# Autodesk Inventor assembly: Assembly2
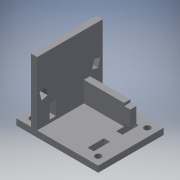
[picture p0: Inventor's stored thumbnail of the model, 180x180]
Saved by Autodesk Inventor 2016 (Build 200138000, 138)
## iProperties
Created: 2017-06
Part Number: Assembly2
Document SubType Name: Assembly
Designer: laboratorioesan
Author: laboratorioesan
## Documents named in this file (4)
- C:\Users\laboratorioesan\Desktop\Proyecto final\FAROS\Assembly2.iam
- C:\Users\laboratorioesan\Desktop\Proyecto final\FAROS\frontal_delantero.ipt
- C:\Users\laboratorioesan\Desktop\Proyecto final\FAROS\Part4.ipt
- C:\Users\laboratorioesan\Desktop\Proyecto final\FAROS\Part5.ipt
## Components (3 placed, 3 different names)
1. frontal_delantero:1 — Flush:1
2. Part4:1 — Flush:1, Flush:2
3. Part5:1 — Flush:2
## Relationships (2: Flush 2)
- Flush:1: frontal_delantero:1 ↔ Part4:1
- Flush:2: Part4:1 ↔ Part5:1
